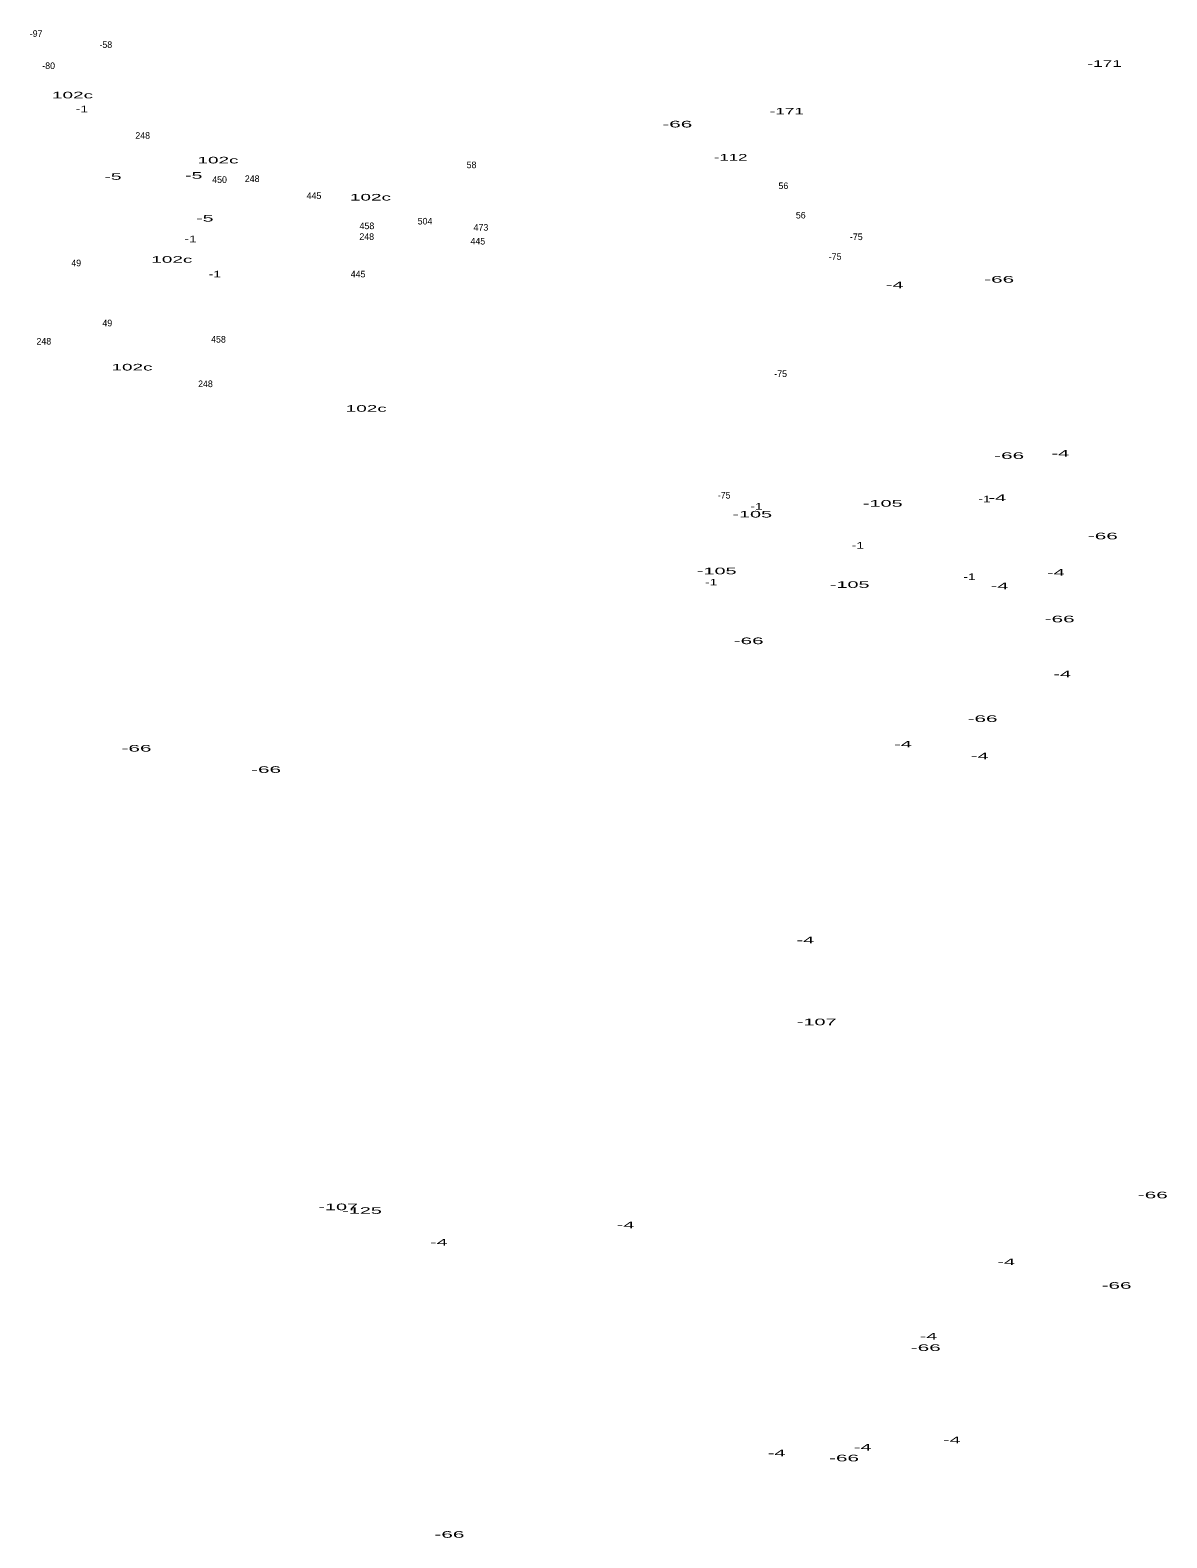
# Model space of a CAD drawing. Extents: x -662280 to -658689, y -991723 to -987042.
# Drawn here: x -660888 to -660198, y -990350 to -989435 of the extents above; entities that cross this region are included whole.
import ezdxf
from ezdxf.enums import TextEntityAlignment as Align

# ---------------------------------------------------------------- set-up
doc = ezdxf.new("R2010")
doc.units = 0
doc.header["$LTSCALE"] = 1.6
doc.layers.add('24', color=7, linetype='Continuous')

msp = doc.modelspace()

# ---------------------------------------------------------------- texts
at = {"layer": '24'}
for s, p in [('-97', (-660884.365, -989439.41)), ('-58', (-660842.075, -989446.14)), ('-80', (-660876.769, -989458.94)), ('248', (-660819.701, -989501.25)), ('248', (-660753.251, -989527.49)), ('58', (-660620.137, -989519.1)), ('450', (-660773.035, -989528.04)), ('56', (-660430.883, -989531.78)), ('445', (-660715.746, -989537.79)), ('504', (-660648.345, -989553.27)), ('56', (-660420.343, -989549.63)), ('458', (-660683.611, -989556.09)), ('248', (-660683.731, -989562.62)), ('473', (-660614.427, -989557.03)), ('-75', (-660386.631, -989562.73)), ('445', (-660616.306, -989565.41)), ('49', (-660860.037, -989578.62)), ('-75', (-660399.471, -989574.73)), ('445', (-660688.976, -989585.38)), ('49', (-660841.177, -989615.07)), ('248', (-660879.681, -989626.12)), ('458', (-660773.701, -989624.93)), ('-75', (-660432.541, -989645.82)), ('248', (-660781.611, -989651.94)), ('-75', (-660466.821, -989719.57))]:
    msp.add_text(s, height=4, dxfattribs=at).set_placement(p, align=Align.CENTER)
for s, width, p in [('-171', 1.95, (-660235.941, -989457.62)), ('102c', 2.15, (-660862.273, -989476.75)), ('-1', 1.55, (-660856.551, -989485.17)), ('-171', 1.95, (-660428.801, -989486.49)), ('-66', 2.35, (-660495.253, -989494.38)), ('102c', 2.15, (-660773.993, -989516.22)), ('-112', 1.9, (-660462.847, -989514.48)), ('-5', 2.2, (-660837.724, -989526.14)), ('-5', 2.2, (-660788.714, -989525.5)), ('102c', 2.15, (-660681.483, -989538.72)), ('-5', 2.2, (-660781.954, -989551.5)), ('-1', 1.55, (-660790.621, -989564.04)), ('102c', 2.15, (-660802.003, -989576.49)), ('-1', 1.55, (-660775.871, -989585.38)), ('-66', 2.35, (-660299.923, -989588.57)), ('-4', 2.25, (-660363.34, -989591.97)), ('102c', 2.15, (-660826.193, -989641.85)), ('102c', 2.15, (-660684.023, -989666.89)), ('-66', 2.35, (-660293.873, -989695.51)), ('-4', 2.25, (-660262.8, -989694.17)), ('-1', 1.55, (-660447.141, -989726.28)), ('-105', 2.25, (-660370.567, -989724.51)), ('-1', 1.55, (-660308.781, -989721.82)), ('-4', 2.25, (-660301.05, -989721.06)), ('-105', 2.25, (-660449.777, -989731.06)), ('-66', 2.35, (-660237.003, -989744.31)), ('-1', 1.55, (-660385.621, -989749.97)), ('-105', 2.25, (-660471.327, -989765.51)), ('-1', 1.55, (-660474.701, -989772.3)), ('-105', 2.25, (-660390.637, -989773.76)), ('-1', 1.55, (-660317.901, -989769)), ('-4', 2.25, (-660299.69, -989774.59)), ('-4', 2.25, (-660265.52, -989766.41)), ('-66', 2.35, (-660263.223, -989794.67)), ('-66', 2.35, (-660451.953, -989807.9)), ('-4', 2.25, (-660261.64, -989828.07)), ('-66', 2.35, (-660310.003, -989855.11)), ('-66', 2.35, (-660823.443, -989873.09)), ('-4', 2.25, (-660358.3, -989870.59)), ('-4', 2.25, (-660311.7, -989877.78)), ('-66', 2.35, (-660744.813, -989886)), ('-4', 2.25, (-660417.58, -989989.48)), ('-107', 2.25, (-660410.661, -990039.15)), ('-66', 2.35, (-660206.693, -990144.17)), ('-107', 2.25, (-660701.031, -990151.36)), ('-125', 2.25, (-660686.591, -990153.57)), ('-4', 2.25, (-660526.64, -990162.34)), ('-4', 2.25, (-660639.97, -990172.83)), ('-4', 2.25, (-660295.66, -990184.71)), ('-66', 2.35, (-660228.673, -990199.04)), ('-4', 2.25, (-660342.81, -990229.86)), ('-66', 2.35, (-660344.463, -990236.78)), ('-4', 2.25, (-660328.65, -990292.77)), ('-4', 2.25, (-660434.99, -990300.73)), ('-66', 2.35, (-660394.073, -990303.77)), ('-4', 2.25, (-660382.79, -990297.24)), ('-66', 2.35, (-660633.533, -990350.13))]:
    msp.add_text(s, height=4, dxfattribs=dict(at, width=width)).set_placement(p, align=Align.CENTER)

doc.saveas('drawing.dxf')
